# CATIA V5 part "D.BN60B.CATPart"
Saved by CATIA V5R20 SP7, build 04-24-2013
Part number: D.BN60B
Material "Nessuno"
Bounding box of the stored display mesh (mm): x 0 to 150.807, y -124.685 to 0, z -91.151 to 75.737
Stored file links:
  C:\Users\designer2\Desktop\Ottobre 2022\25-10-2022\04\Yori Evo 48V\D.BN60B.CATPart
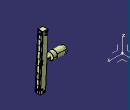
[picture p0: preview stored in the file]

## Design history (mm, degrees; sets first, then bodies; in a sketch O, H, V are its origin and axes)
AxisSystem1: origin (0, 0, 0), X (1, 0, 0), Y (0, 1, 0), Z (0, 0, 1)
Set1
  DatumSurface1
Body1 (main body), material "Nessuno"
